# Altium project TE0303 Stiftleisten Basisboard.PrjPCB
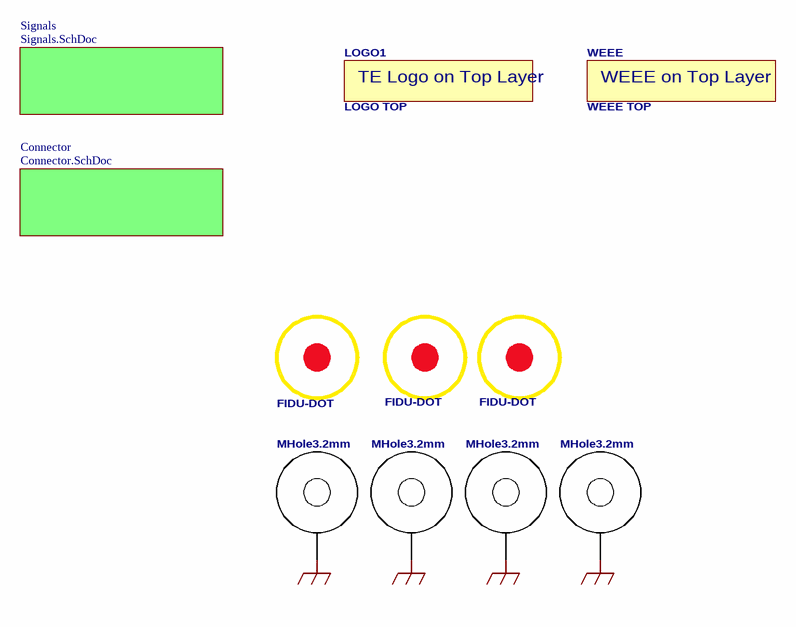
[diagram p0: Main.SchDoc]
3 sheets, 42 parts. Net scope: global (net labels, ports and power ports of the same name join across sheets).
Board file: TE0303.PcbDoc
Sheets:
  Main.SchDoc
    Connector = Connector.SchDoc
    Signals = Signals.SchDoc

## Sheet Main.SchDoc: Header Baseboard - Main Sheet
size A4; Organization: Trenz Electronic GmbH; DocumentNumber: TE0303; Revision: 01; SheetNumber: 1; SheetTotal: 3; Date: 2010-03-19

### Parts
H1  MHole3.2mm  [MHole3_2mm]  (no BOM)
H2  MHole3.2mm  [MHole3_2mm]  (no BOM)
H3  MHole3.2mm  [MHole3_2mm]  (no BOM)
H4  MHole3.2mm  [MHole3_2mm]  (no BOM)
LOGO1  LOGO TOP  [Logo Top]  (no BOM)
PM1  FIDU-DOT  [FIDU-DOT]
PM2  FIDU-DOT  [FIDU-DOT]
PM3  FIDU-DOT  [FIDU-DOT]
WEEE  WEEE TOP  [WEEETOP_10_25mm]  (no BOM)

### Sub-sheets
Connector = Connector.SchDoc: no entries
Signals = Signals.SchDoc: no entries

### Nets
FGND: H1.1 H2.1 H3.1 H4.1

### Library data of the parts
H1-H4 = 22898: AN: 22898
LOGO1 = 22901: AN: 22901
PM1-PM3 = 22906: AN: 22906
WEEE = 22300: AN: 22300; Bezeichnung: WEEE TOP (10.25mm)

## Sheet Connector.SchDoc: Header Baseboard - Headers
size A4; Organization: Trenz Electronic GmbH; DocumentNumber: TE0303; Revision: 01; SheetNumber: 3; SheetTotal: 3; Date: 2010-03-19
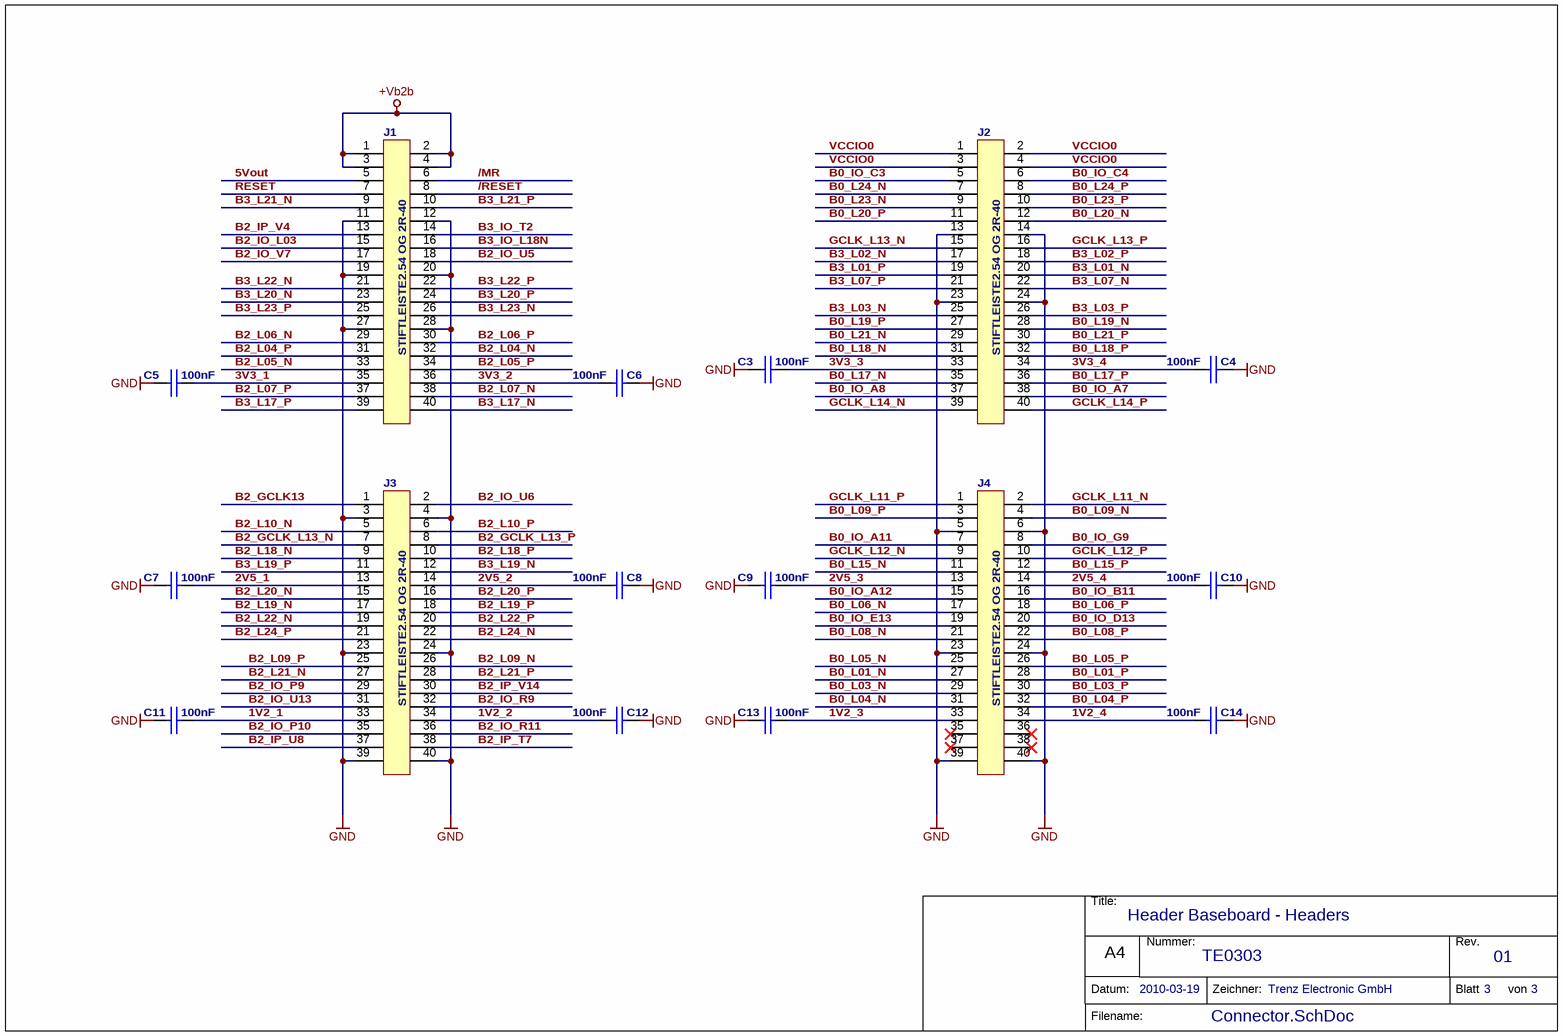
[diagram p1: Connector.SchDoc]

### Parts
C3  100nF  [CAPC1608N]
C4  100nF  [CAPC1608N]
C5  100nF  [CAPC1608N]
C6  100nF  [CAPC1608N]
C7  100nF  [CAPC1608N]
C8  100nF  [CAPC1608N]
C9  100nF  [CAPC1608N]
C10  100nF  [CAPC1608N]
C11  100nF  [CAPC1608N]
C12  100nF  [CAPC1608N]
C13  100nF  [CAPC1608N]
C14  100nF  [CAPC1608N]
J1  STIFTLEISTE2.54 OG 2R-40  [STIFTLEISTE2_54 OG 2R-40]
J2  STIFTLEISTE2.54 OG 2R-40  [STIFTLEISTE2_54 OG 2R-40]
J3  STIFTLEISTE2.54 OG 2R-40  [STIFTLEISTE2_54 OG 2R-40]
J4  STIFTLEISTE2.54 OG 2R-40  [STIFTLEISTE2_54 OG 2R-40]

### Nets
+Vb2b: J1.1 J1.2 J1.3 J1.4
GND: C3.2 C4.2 C5.2 C6.2 C7.2 C8.2 C9.2 C10.2 C11.2 C12.2 C13.2 C14.2 J1.11 J1.12 J1.19 J1.20 J1.27 J1.28 J2.13 J2.14 J2.23 J2.24 J3.3 J3.4 J3.23 J3.24 J3.39 J3.40 J4.5 J4.6 J4.23 J4.24 J4.39 J4.40
1V2_1: C11.1 J3.33
1V2_2: C12.1 J3.34
1V2_3: C13.1 J4.33
1V2_4: C14.1 J4.34
2V5_1: C7.1 J3.13
2V5_2: C8.1 J3.14
2V5_3: C9.1 J4.13
2V5_4: C10.1 J4.14
3V3_1: C5.1 J1.35
3V3_2: C6.1 J1.36
3V3_3: C3.1 J2.33
3V3_4: C4.1 J2.34
5Vout: J1.5
/MR: J1.6
/RESET: J1.8
B0_IO_A7: J2.38
B0_IO_A8: J2.37
B0_IO_A11: J4.7
B0_IO_A12: J4.15
B0_IO_B11: J4.16
B0_IO_C3: J2.5
B0_IO_C4: J2.6
B0_IO_D13: J4.20
B0_IO_E13: J4.19
B0_IO_G9: J4.8
B0_L01_N: J4.27
B0_L01_P: J4.28
B0_L03_N: J4.29
B0_L03_P: J4.30
B0_L04_N: J4.31
B0_L04_P: J4.32
B0_L05_N: J4.25
B0_L05_P: J4.26
B0_L06_N: J4.17
B0_L06_P: J4.18
B0_L08_N: J4.21
B0_L08_P: J4.22
B0_L09_N: J4.4
B0_L09_P: J4.3
B0_L15_N: J4.11
B0_L15_P: J4.12
B0_L17_N: J2.35
B0_L17_P: J2.36
B0_L18_N: J2.31
B0_L18_P: J2.32
B0_L19_N: J2.28
B0_L19_P: J2.27
B0_L20_N: J2.12
B0_L20_P: J2.11
B0_L21_N: J2.29
B0_L21_P: J2.30
B0_L23_N: J2.9
B0_L23_P: J2.10
B0_L24_N: J2.7
B0_L24_P: J2.8
B2_GCLK13: J3.1
B2_GCLK_L13_N: J3.7
B2_GCLK_L13_P: J3.8
B2_IO_L03: J1.15
B2_IO_P9: J3.29
B2_IO_P10: J3.35
B2_IO_R9: J3.32
B2_IO_R11: J3.36
B2_IO_U5: J1.18
B2_IO_U6: J3.2
B2_IO_U13: J3.31
B2_IO_V7: J1.17
B2_IP_T7: J3.38
B2_IP_U8: J3.37
B2_IP_V4: J1.13
B2_IP_V14: J3.30
B2_L04_N: J1.32
B2_L04_P: J1.31
B2_L05_N: J1.33
B2_L05_P: J1.34
B2_L06_N: J1.29
B2_L06_P: J1.30
B2_L07_N: J1.38
B2_L07_P: J1.37
B2_L09_N: J3.26
B2_L09_P: J3.25
B2_L10_N: J3.5
B2_L10_P: J3.6
B2_L18_N: J3.9
B2_L18_P: J3.10
B2_L19_N: J3.17
B2_L19_P: J3.18
B2_L20_N: J3.15
B2_L20_P: J3.16
B2_L21_N: J3.27
B2_L21_P: J3.28
B2_L22_N: J3.19
B2_L22_P: J3.20
B2_L24_N: J3.22
B2_L24_P: J3.21
B3_IO_L18N: J1.16
B3_IO_T2: J1.14
B3_L01_N: J2.20
B3_L01_P: J2.19
B3_L02_N: J2.17
B3_L02_P: J2.18
B3_L03_N: J2.25
B3_L03_P: J2.26
B3_L07_N: J2.22
B3_L07_P: J2.21
B3_L17_N: J1.40
B3_L17_P: J1.39
B3_L19_N: J3.12
B3_L19_P: J3.11
B3_L20_N: J1.23
B3_L20_P: J1.24
B3_L21_N: J1.9
B3_L21_P: J1.10
B3_L22_N: J1.21
B3_L22_P: J1.22
B3_L23_N: J1.26
B3_L23_P: J1.25
GCLK_L11_N: J4.2
GCLK_L11_P: J4.1
GCLK_L12_N: J4.9
GCLK_L12_P: J4.10
GCLK_L13_N: J2.15
GCLK_L13_P: J2.16
GCLK_L14_N: J2.39
GCLK_L14_P: J2.40
RESET: J1.7
VCCIO0: J2.1 J2.2 J2.3 J2.4

Not connected (* = marked no-connect by the designer): J4 35* 36* 37* 38*

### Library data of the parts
C3-C14 = 21382: AN: 21382; Bezeichnung: KON 100nF 16V X7R SMD; Param 1: 16V; Param 2: X7R; Value: 100n
J1-J4 = 22320: AN: 22320; Bezeichnung: Stiftleiste gerade 2-reihig, 40pol

## Sheet Signals.SchDoc: Header Baseboard - TE0140 Module
size A4; Organization: Trenz Electronic GmbH; DocumentNumber: TE0303; Revision: 01; SheetNumber: 2; SheetTotal: 3; Date: 2010-03-19
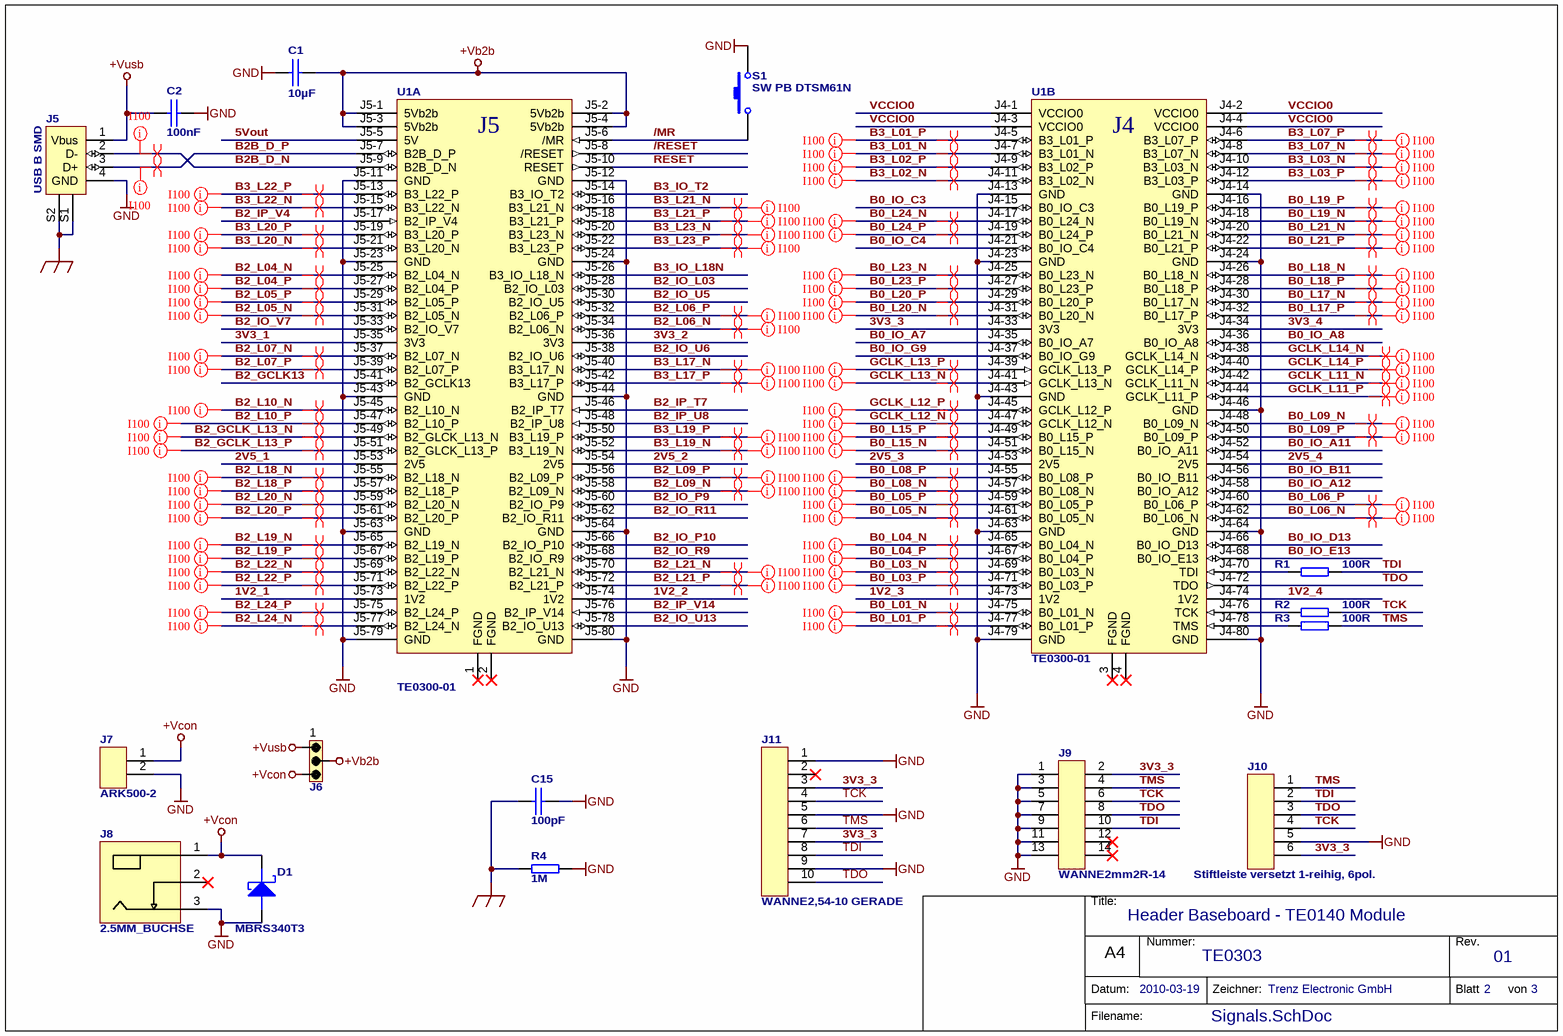
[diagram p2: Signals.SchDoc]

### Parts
C1  10µF  [CAPC2012N]
C2  100nF  [CAPC1608N]
C15  100pF  [CAPC3216N]
D1  MBRS340T3  [MBRS340T3]
J5  USB B SMD  [USB B SMD]
J6  JUMPER2.54-3  [JUMPER2_54-3]  (value not drawn)
J7  ARK500-2  [ARK500-2]
J8  2.5MM_BUCHSE  [WS-DC001]
J9  WANNE2mm2R-14  [WANNE2mm2R-14]
J10  Stiftleiste versetzt 1-reihig, 6pol.  [STIFTLEISTE2_54 OG 1R-6V]
J11  WANNE2,54-10 GERADE  [WANNE2,54-10 GERADE]
R1  100R  [RESC1005N]
R2  100R  [RESC1005N]
R3  100R  [RESC1005N]
R4  1M  [RESC3216N]
S1  SW PB DTSM61N  [DTSM61N]
U1  TE0300-01  [TE0300-01]  (parts A,B of 2)

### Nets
+Vb2b: C1.2 J6.2 U1.J5-1(5Vb2b) U1.J5-2(5Vb2b) U1.J5-3(5Vb2b) U1.J5-4(5Vb2b)
+Vcon: D1.1(CATHODE) J6.3 J7.1 J8.1
+Vusb: C2.1 J5.1(Vbus) J6.1
FGND: C15.1 J5.S1 J5.S2 R4.1
GND: C1.1 C2.2 C15.2 D1.2(ANODE) J5.4(GND) J7.2 J8.3 J9.1 J9.3 J9.5 J9.7 J9.9 J9.11 J9.13 J10.5 J11.1 J11.5 J11.9 R4.2 S1.2 U1.J4-13(GND) U1.J4-14(GND) U1.J4-23(GND) U1.J4-24(GND) U1.J4-43(GND) U1.J4-46(GND) U1.J4-63(GND) U1.J4-64(GND) U1.J4-79(GND) U1.J4-80(GND) U1.J5-11(GND) U1.J5-12(GND) U1.J5-23(GND) U1.J5-24(GND) U1.J5-43(GND) U1.J5-44(GND) U1.J5-63(GND) U1.J5-64(GND) U1.J5-79(GND) U1.J5-80(GND)
1V2_1: U1.J5-73(1V2)
1V2_2: U1.J5-74(1V2)
1V2_3: U1.J4-73(1V2)
1V2_4: U1.J4-74(1V2)
2V5_1: U1.J5-53(2V5)
2V5_2: U1.J5-54(2V5)
2V5_3: U1.J4-53(2V5)
2V5_4: U1.J4-54(2V5)
3V3_1: U1.J5-35(3V3)
3V3_2: U1.J5-36(3V3)
3V3_3: J9.2 J10.6 J11.3 J11.7 U1.J4-33(3V3)
3V3_4: U1.J4-34(3V3)
5Vout: U1.J5-5(5V)
/MR: S1.1 U1.J5-6(/MR)
/RESET: U1.J5-8(/RESET)
B0_IO_A7: U1.J4-35(B0_IO_A7)
B0_IO_A8: U1.J4-36(B0_IO_A8)
B0_IO_A11: U1.J4-52(B0_IO_A11)
B0_IO_A12: U1.J4-58(B0_IO_A12)
B0_IO_B11: U1.J4-56(B0_IO_B11)
B0_IO_C3: U1.J4-15(B0_IO_C3)
B0_IO_C4: U1.J4-21(B0_IO_C4)
B0_IO_D13: U1.J4-66(B0_IO_D13)
B0_IO_E13: U1.J4-68(B0_IO_E13)
B0_IO_G9: U1.J4-37(B0_IO_G9)
B0_L01_N: U1.J4-75(B0_L01_N)
B0_L01_P: U1.J4-77(B0_L01_P)
B0_L03_N: U1.J4-69(B0_L03_N)
B0_L03_P: U1.J4-71(B0_L03_P)
B0_L04_N: U1.J4-65(B0_L04_N)
B0_L04_P: U1.J4-67(B0_L04_P)
B0_L05_N: U1.J4-61(B0_L05_N)
B0_L05_P: U1.J4-59(B0_L05_P)
B0_L06_N: U1.J4-62(B0_L06_N)
B0_L06_P: U1.J4-60(B0_L06_P)
B0_L08_N: U1.J4-57(B0_L08_N)
B0_L08_P: U1.J4-55(B0_L08_P)
B0_L09_N: U1.J4-48(B0_L09_N)
B0_L09_P: U1.J4-50(B0_L09_P)
B0_L15_N: U1.J4-51(B0_L15_N)
B0_L15_P: U1.J4-49(B0_L15_P)
B0_L17_N: U1.J4-30(B0_L17_N)
B0_L17_P: U1.J4-32(B0_L17_P)
B0_L18_N: U1.J4-26(B0_L18_N)
B0_L18_P: U1.J4-28(B0_L18_P)
B0_L19_N: U1.J4-18(B0_L19_N)
B0_L19_P: U1.J4-16(B0_L19_P)
B0_L20_N: U1.J4-31(B0_L20_N)
B0_L20_P: U1.J4-29(B0_L20_P)
B0_L21_N: U1.J4-20(B0_L21_N)
B0_L21_P: U1.J4-22(B0_L21_P)
B0_L23_N: U1.J4-25(B0_L23_N)
B0_L23_P: U1.J4-27(B0_L23_P)
B0_L24_N: U1.J4-17(B0_L24_N)
B0_L24_P: U1.J4-19(B0_L24_P)
B2_GCLK13: U1.J5-41(B2_GCLK13)
B2_GCLK_L13_N: U1.J5-49(B2_GLCK_L13_N)
B2_GCLK_L13_P: U1.J5-51(B2_GLCK_L13_P)
B2_IO_L03: U1.J5-28(B2_IO_L03)
B2_IO_P9: U1.J5-60(B2_IO_P9)
B2_IO_P10: U1.J5-66(B2_IO_P10)
B2_IO_R9: U1.J5-68(B2_IO_R9)
B2_IO_R11: U1.J5-62(B2_IO_R11)
B2_IO_U5: U1.J5-30(B2_IO_U5)
B2_IO_U6: U1.J5-38(B2_IO_U6)
B2_IO_U13: U1.J5-78(B2_IO_U13)
B2_IO_V7: U1.J5-33(B2_IO_V7)
B2_IP_T7: U1.J5-46(B2_IP_T7)
B2_IP_U8: U1.J5-48(B2_IP_U8)
B2_IP_V4: U1.J5-17(B2_IP_V4)
B2_IP_V14: U1.J5-76(B2_IP_V14)
B2_L04_N: U1.J5-25(B2_L04_N)
B2_L04_P: U1.J5-27(B2_L04_P)
B2_L05_N: U1.J5-31(B2_L05_N)
B2_L05_P: U1.J5-29(B2_L05_P)
B2_L06_N: U1.J5-34(B2_L06_N)
B2_L06_P: U1.J5-32(B2_L06_P)
B2_L07_N: U1.J5-37(B2_L07_N)
B2_L07_P: U1.J5-39(B2_L07_P)
B2_L09_N: U1.J5-58(B2_L09_N)
B2_L09_P: U1.J5-56(B2_L09_P)
B2_L10_N: U1.J5-45(B2_L10_N)
B2_L10_P: U1.J5-47(B2_L10_P)
B2_L18_N: U1.J5-55(B2_L18_N)
B2_L18_P: U1.J5-57(B2_L18_P)
B2_L19_N: U1.J5-65(B2_L19_N)
B2_L19_P: U1.J5-67(B2_L19_P)
B2_L20_N: U1.J5-59(B2_L20_N)
B2_L20_P: U1.J5-61(B2_L20_P)
B2_L21_N: U1.J5-70(B2_L21_N)
B2_L21_P: U1.J5-72(B2_L21_P)
B2_L22_N: U1.J5-69(B2_L22_N)
B2_L22_P: U1.J5-71(B2_L22_P)
B2_L24_N: U1.J5-77(B2_L24_N)
B2_L24_P: U1.J5-75(B2_L24_P)
B2B_D_N: J5.2(D-) U1.J5-9(B2B_D_N)
B2B_D_P: J5.3(D+) U1.J5-7(B2B_D_P)
B3_IO_L18N: U1.J5-26(B3_IO_L18_N)
B3_IO_T2: U1.J5-14(B3_IO_T2)
B3_L01_N: U1.J4-7(B3_L01_N)
B3_L01_P: U1.J4-5(B3_L01_P)
B3_L02_N: U1.J4-11(B3_L02_N)
B3_L02_P: U1.J4-9(B3_L02_P)
B3_L03_N: U1.J4-10(B3_L03_N)
B3_L03_P: U1.J4-12(B3_L03_P)
B3_L07_N: U1.J4-8(B3_L07_N)
B3_L07_P: U1.J4-6(B3_L07_P)
B3_L17_N: U1.J5-40(B3_L17_N)
B3_L17_P: U1.J5-42(B3_L17_P)
B3_L19_N: U1.J5-52(B3_L19_N)
B3_L19_P: U1.J5-50(B3_L19_P)
B3_L20_N: U1.J5-21(B3_L20_N)
B3_L20_P: U1.J5-19(B3_L20_P)
B3_L21_N: U1.J5-16(B3_L21_N)
B3_L21_P: U1.J5-18(B3_L21_P)
B3_L22_N: U1.J5-15(B3_L22_N)
B3_L22_P: U1.J5-13(B3_L22_P)
B3_L23_N: U1.J5-20(B3_L23_N)
B3_L23_P: U1.J5-22(B3_L23_P)
GCLK_L11_N: U1.J4-42(GCLK_L11_N)
GCLK_L11_P: U1.J4-44(GCLK_L11_P)
GCLK_L12_N: U1.J4-47(GCLK_L12_N)
GCLK_L12_P: U1.J4-45(GCLK_L12_P)
GCLK_L13_N: U1.J4-41(GCLK_L13_N)
GCLK_L13_P: U1.J4-39(GCLK_L13_P)
GCLK_L14_N: U1.J4-38(GCLK_L14_N)
GCLK_L14_P: U1.J4-40(GCLK_L14_P)
RESET: U1.J5-10(RESET)
TCK: J9.6 J10.4 J11.4 R2.2
TDI: J9.10 J10.2 J11.8 R1.2
TDO: J9.8 J10.3 J11.10 U1.J4-72(TDO)
TMS: J9.4 J10.1 J11.6 R3.2
VCCIO0: U1.J4-1(VCCIO0) U1.J4-2(VCCIO0) U1.J4-3(VCCIO0) U1.J4-4(VCCIO0)
NetR1_1: R1.1 U1.J4-70(TDI)
NetR2_1: R2.1 U1.J4-76(TCK)
NetR3_1: R3.1 U1.J4-78(TMS)

Not connected (* = marked no-connect by the designer): J8 2*; J9 12* 14*; J11 2*; U1 1(FGND)* 2(FGND)* 3(FGND)* 4(FGND)*

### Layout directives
net class I100: B0_L01_N, B0_L01_P, B0_L03_N, B0_L03_P, B0_L04_N, B0_L04_P, B0_L05_N, B0_L05_P, B0_L06_N, B0_L06_P, B0_L08_N, B0_L08_P, B0_L09_N, B0_L09_P, B0_L15_N, B0_L15_P, B0_L17_N, B0_L17_P, B0_L18_N, B0_L18_P, B0_L19_N, B0_L19_P, B0_L20_N, B0_L20_P, B0_L21_N, B0_L21_P, B0_L23_N, B0_L23_P, B0_L24_N, B0_L24_P, B2_GCLK_L13_N, B2_GCLK_L13_P, B2_L04_N, B2_L04_P, B2_L05_N, B2_L05_P, B2_L06_N, B2_L06_P, B2_L07_N, B2_L07_P, B2_L09_N, B2_L09_P, B2_L10_N, B2_L10_P, B2_L18_N, B2_L18_P, B2_L19_N, B2_L19_P, B2_L20_N, B2_L20_P, B2_L21_N, B2_L21_P, B2_L22_N, B2_L22_P, B2_L24_N, B2_L24_P, B2B_D_N, B2B_D_P, B3_L01_N, B3_L01_P, B3_L02_N, B3_L02_P, B3_L03_N, B3_L03_P, B3_L07_N, B3_L07_P, B3_L17_N, B3_L17_P, B3_L19_N, B3_L19_P, B3_L20_N, B3_L20_P, B3_L21_N, B3_L21_P, B3_L22_N, B3_L22_P, B3_L23_N, B3_L23_P, GCLK_L11_N, GCLK_L11_P, GCLK_L12_N, GCLK_L12_P, GCLK_L13_N, GCLK_L13_P, GCLK_L14_N, GCLK_L14_P
differential pair: B0_L01_N, B0_L01_P, B0_L03_N, B0_L03_P, B0_L04_N, B0_L04_P, B0_L05_N, B0_L05_P, B0_L06_N, B0_L06_P, B0_L08_N, B0_L08_P, B0_L09_N, B0_L09_P, B0_L15_N, B0_L15_P, B0_L17_N, B0_L17_P, B0_L18_N, B0_L18_P, B0_L19_N, B0_L19_P, B0_L20_N, B0_L20_P, B0_L21_N, B0_L21_P, B0_L23_N, B0_L23_P, B0_L24_N, B0_L24_P, B2_GCLK_L13_N, B2_GCLK_L13_P, B2_L04_N, B2_L04_P, B2_L05_N, B2_L05_P, B2_L06_N, B2_L06_P, B2_L07_N, B2_L07_P, B2_L09_N, B2_L09_P, B2_L10_N, B2_L10_P, B2_L18_N, B2_L18_P, B2_L19_N, B2_L19_P, B2_L20_N, B2_L20_P, B2_L21_N, B2_L21_P, B2_L22_N, B2_L22_P, B2_L24_N, B2_L24_P, B2B_D_N, B2B_D_P, B3_L01_N, B3_L01_P, B3_L02_N, B3_L02_P, B3_L03_N, B3_L03_P, B3_L07_N, B3_L07_P, B3_L17_N, B3_L17_P, B3_L19_N, B3_L19_P, B3_L20_N, B3_L20_P, B3_L21_N, B3_L21_P, B3_L22_N, B3_L22_P, B3_L23_N, B3_L23_P, GCLK_L11_N, GCLK_L11_P, GCLK_L12_N, GCLK_L12_P, GCLK_L13_N, GCLK_L13_P, GCLK_L14_N, GCLK_L14_P

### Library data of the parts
C1 = 22478: AN: 22478; Bezeichnung: KON 10µF 6,3V  X5R SMD; Param 1: 6.3V; Param 2: X5R; Value: 10u
C2 = 21382: as C3 on sheet Connector
C15 = 22679: AN: 22679; Bezeichnung: KON 100pF; Value: 100p
D1 = 22887: AN: 22887; Bezeichnung: MBRS340T3 SMD
J5 = 22990: AN: 22990; Bezeichnung: STE USB B LP Buchse SMD
J6 = 22328: Jumper; AN: 22328; Bezeichnung: Stiftleiste gerade 1-reihig, 3pol.
J7 = 20123: AN: 20123; Bezeichnung: Schraubklemme LP 2 pol ARK500-2
J8 = 22398: 2.5mm Stromversorgungsbuchse; AN: 22398; Bezeichnung: STE 2,5mm Buchse WIESON
J9 = 22744: AN: 22744; Bezeichnung: Stiftleiste Wanne 14polig
J10 = 22911: AN: 22911
J11 = 20125: AN: 20125; Bezeichnung: Stiftleiste Wanne 10polig
R1-R3 = 22507: AN: 22507; Bezeichnung: WID SMD 100R 1% 0,063W; Value: 100
R4 = 22757: AN: 22757; Bezeichnung: WID SMD 1M
S1 = 22596: AN: 22596; Bezeichnung: Taster Miniatur Leiterplatte 1.6N
U1 = TE0300-01BM: Spartan-3E Micromodul

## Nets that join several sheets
+Vb2b: Connector (J1.1 J1.2 J1.3 J1.4), Signals (6 pins)
FGND: Main (H1.1 H2.1 H3.1 H4.1), Signals (C15.1 J5.S1 J5.S2 R4.1)
GND: Connector (34 pins), Signals (40 pins)
1V2_1: Connector (C11.1 J3.33), Signals (U1.J5-73)
1V2_2: Connector (C12.1 J3.34), Signals (U1.J5-74)
1V2_3: Connector (C13.1 J4.33), Signals (U1.J4-73)
1V2_4: Connector (C14.1 J4.34), Signals (U1.J4-74)
2V5_1: Connector (C7.1 J3.13), Signals (U1.J5-53)
2V5_2: Connector (C8.1 J3.14), Signals (U1.J5-54)
2V5_3: Connector (C9.1 J4.13), Signals (U1.J4-53)
2V5_4: Connector (C10.1 J4.14), Signals (U1.J4-54)
3V3_1: Connector (C5.1 J1.35), Signals (U1.J5-35)
3V3_2: Connector (C6.1 J1.36), Signals (U1.J5-36)
3V3_3: Connector (C3.1 J2.33), Signals (5 pins)
3V3_4: Connector (C4.1 J2.34), Signals (U1.J4-34)
5Vout: Connector (J1.5), Signals (U1.J5-5)
/MR: Connector (J1.6), Signals (S1.1 U1.J5-6)
/RESET: Connector (J1.8), Signals (U1.J5-8)
B0_IO_A7: Connector (J2.38), Signals (U1.J4-35)
B0_IO_A8: Connector (J2.37), Signals (U1.J4-36)
B0_IO_A11: Connector (J4.7), Signals (U1.J4-52)
B0_IO_A12: Connector (J4.15), Signals (U1.J4-58)
B0_IO_B11: Connector (J4.16), Signals (U1.J4-56)
B0_IO_C3: Connector (J2.5), Signals (U1.J4-15)
B0_IO_C4: Connector (J2.6), Signals (U1.J4-21)
B0_IO_D13: Connector (J4.20), Signals (U1.J4-66)
B0_IO_E13: Connector (J4.19), Signals (U1.J4-68)
B0_IO_G9: Connector (J4.8), Signals (U1.J4-37)
B0_L01_N: Connector (J4.27), Signals (U1.J4-75)
B0_L01_P: Connector (J4.28), Signals (U1.J4-77)
B0_L03_N: Connector (J4.29), Signals (U1.J4-69)
B0_L03_P: Connector (J4.30), Signals (U1.J4-71)
B0_L04_N: Connector (J4.31), Signals (U1.J4-65)
B0_L04_P: Connector (J4.32), Signals (U1.J4-67)
B0_L05_N: Connector (J4.25), Signals (U1.J4-61)
B0_L05_P: Connector (J4.26), Signals (U1.J4-59)
B0_L06_N: Connector (J4.17), Signals (U1.J4-62)
B0_L06_P: Connector (J4.18), Signals (U1.J4-60)
B0_L08_N: Connector (J4.21), Signals (U1.J4-57)
B0_L08_P: Connector (J4.22), Signals (U1.J4-55)
B0_L09_N: Connector (J4.4), Signals (U1.J4-48)
B0_L09_P: Connector (J4.3), Signals (U1.J4-50)
B0_L15_N: Connector (J4.11), Signals (U1.J4-51)
B0_L15_P: Connector (J4.12), Signals (U1.J4-49)
B0_L17_N: Connector (J2.35), Signals (U1.J4-30)
B0_L17_P: Connector (J2.36), Signals (U1.J4-32)
B0_L18_N: Connector (J2.31), Signals (U1.J4-26)
B0_L18_P: Connector (J2.32), Signals (U1.J4-28)
B0_L19_N: Connector (J2.28), Signals (U1.J4-18)
B0_L19_P: Connector (J2.27), Signals (U1.J4-16)
B0_L20_N: Connector (J2.12), Signals (U1.J4-31)
B0_L20_P: Connector (J2.11), Signals (U1.J4-29)
B0_L21_N: Connector (J2.29), Signals (U1.J4-20)
B0_L21_P: Connector (J2.30), Signals (U1.J4-22)
B0_L23_N: Connector (J2.9), Signals (U1.J4-25)
B0_L23_P: Connector (J2.10), Signals (U1.J4-27)
B0_L24_N: Connector (J2.7), Signals (U1.J4-17)
B0_L24_P: Connector (J2.8), Signals (U1.J4-19)
B2_GCLK13: Connector (J3.1), Signals (U1.J5-41)
B2_GCLK_L13_N: Connector (J3.7), Signals (U1.J5-49)
B2_GCLK_L13_P: Connector (J3.8), Signals (U1.J5-51)
B2_IO_L03: Connector (J1.15), Signals (U1.J5-28)
B2_IO_P9: Connector (J3.29), Signals (U1.J5-60)
B2_IO_P10: Connector (J3.35), Signals (U1.J5-66)
B2_IO_R9: Connector (J3.32), Signals (U1.J5-68)
B2_IO_R11: Connector (J3.36), Signals (U1.J5-62)
B2_IO_U5: Connector (J1.18), Signals (U1.J5-30)
B2_IO_U6: Connector (J3.2), Signals (U1.J5-38)
B2_IO_U13: Connector (J3.31), Signals (U1.J5-78)
B2_IO_V7: Connector (J1.17), Signals (U1.J5-33)
B2_IP_T7: Connector (J3.38), Signals (U1.J5-46)
B2_IP_U8: Connector (J3.37), Signals (U1.J5-48)
B2_IP_V4: Connector (J1.13), Signals (U1.J5-17)
B2_IP_V14: Connector (J3.30), Signals (U1.J5-76)
B2_L04_N: Connector (J1.32), Signals (U1.J5-25)
B2_L04_P: Connector (J1.31), Signals (U1.J5-27)
B2_L05_N: Connector (J1.33), Signals (U1.J5-31)
B2_L05_P: Connector (J1.34), Signals (U1.J5-29)
B2_L06_N: Connector (J1.29), Signals (U1.J5-34)
B2_L06_P: Connector (J1.30), Signals (U1.J5-32)
B2_L07_N: Connector (J1.38), Signals (U1.J5-37)
B2_L07_P: Connector (J1.37), Signals (U1.J5-39)
B2_L09_N: Connector (J3.26), Signals (U1.J5-58)
B2_L09_P: Connector (J3.25), Signals (U1.J5-56)
B2_L10_N: Connector (J3.5), Signals (U1.J5-45)
B2_L10_P: Connector (J3.6), Signals (U1.J5-47)
B2_L18_N: Connector (J3.9), Signals (U1.J5-55)
B2_L18_P: Connector (J3.10), Signals (U1.J5-57)
B2_L19_N: Connector (J3.17), Signals (U1.J5-65)
B2_L19_P: Connector (J3.18), Signals (U1.J5-67)
B2_L20_N: Connector (J3.15), Signals (U1.J5-59)
B2_L20_P: Connector (J3.16), Signals (U1.J5-61)
B2_L21_N: Connector (J3.27), Signals (U1.J5-70)
B2_L21_P: Connector (J3.28), Signals (U1.J5-72)
B2_L22_N: Connector (J3.19), Signals (U1.J5-69)
B2_L22_P: Connector (J3.20), Signals (U1.J5-71)
B2_L24_N: Connector (J3.22), Signals (U1.J5-77)
B2_L24_P: Connector (J3.21), Signals (U1.J5-75)
B3_IO_L18N: Connector (J1.16), Signals (U1.J5-26)
B3_IO_T2: Connector (J1.14), Signals (U1.J5-14)
B3_L01_N: Connector (J2.20), Signals (U1.J4-7)
B3_L01_P: Connector (J2.19), Signals (U1.J4-5)
B3_L02_N: Connector (J2.17), Signals (U1.J4-11)
B3_L02_P: Connector (J2.18), Signals (U1.J4-9)
B3_L03_N: Connector (J2.25), Signals (U1.J4-10)
B3_L03_P: Connector (J2.26), Signals (U1.J4-12)
B3_L07_N: Connector (J2.22), Signals (U1.J4-8)
B3_L07_P: Connector (J2.21), Signals (U1.J4-6)
B3_L17_N: Connector (J1.40), Signals (U1.J5-40)
B3_L17_P: Connector (J1.39), Signals (U1.J5-42)
B3_L19_N: Connector (J3.12), Signals (U1.J5-52)
B3_L19_P: Connector (J3.11), Signals (U1.J5-50)
B3_L20_N: Connector (J1.23), Signals (U1.J5-21)
B3_L20_P: Connector (J1.24), Signals (U1.J5-19)
B3_L21_N: Connector (J1.9), Signals (U1.J5-16)
B3_L21_P: Connector (J1.10), Signals (U1.J5-18)
B3_L22_N: Connector (J1.21), Signals (U1.J5-15)
B3_L22_P: Connector (J1.22), Signals (U1.J5-13)
B3_L23_N: Connector (J1.26), Signals (U1.J5-20)
B3_L23_P: Connector (J1.25), Signals (U1.J5-22)
GCLK_L11_N: Connector (J4.2), Signals (U1.J4-42)
GCLK_L11_P: Connector (J4.1), Signals (U1.J4-44)
GCLK_L12_N: Connector (J4.9), Signals (U1.J4-47)
GCLK_L12_P: Connector (J4.10), Signals (U1.J4-45)
GCLK_L13_N: Connector (J2.15), Signals (U1.J4-41)
GCLK_L13_P: Connector (J2.16), Signals (U1.J4-39)
GCLK_L14_N: Connector (J2.39), Signals (U1.J4-38)
GCLK_L14_P: Connector (J2.40), Signals (U1.J4-40)
RESET: Connector (J1.7), Signals (U1.J5-10)
VCCIO0: Connector (J2.1 J2.2 J2.3 J2.4), Signals (U1.J4-1 U1.J4-2 U1.J4-3 U1.J4-4)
